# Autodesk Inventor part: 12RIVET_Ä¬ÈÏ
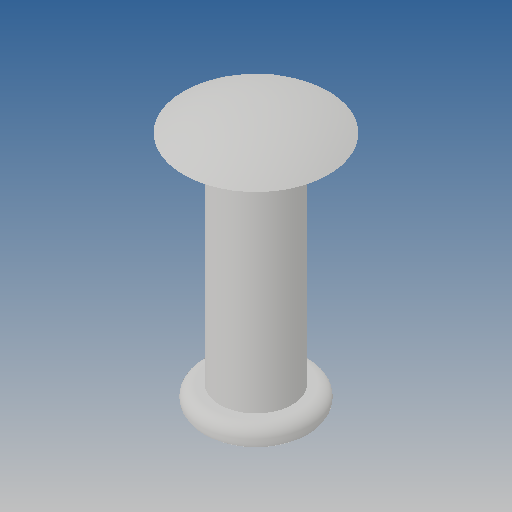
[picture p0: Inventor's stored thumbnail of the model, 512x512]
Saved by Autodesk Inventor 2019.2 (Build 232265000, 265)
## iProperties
Created: 2010-06
Part Number: 12RIVET_Ä¬ÈÏ
Material: Ogólny
Document SubType Name: Modeling
Designer: CADENGINEERING4
Density: 1 g/cm^3
Appearance: Domyślna
Author: CADENGINEERING4
Revision Number: ÈÎºÎ
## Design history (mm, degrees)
feature "NONE"
node "Bryła1"
